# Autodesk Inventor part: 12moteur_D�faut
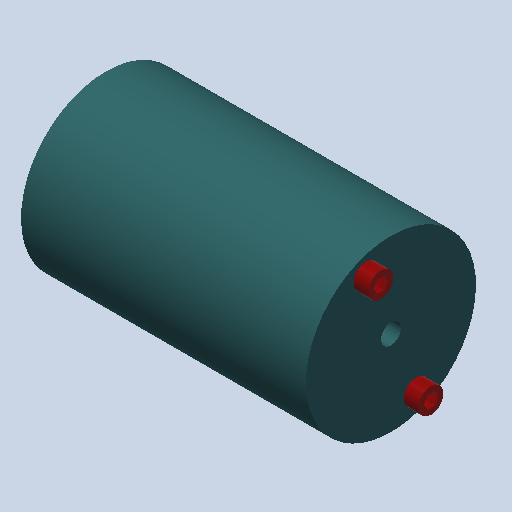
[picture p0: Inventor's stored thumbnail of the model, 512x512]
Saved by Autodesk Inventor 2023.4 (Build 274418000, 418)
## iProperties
Created: 2011-01
Part Number: 12moteur_D�faut
Document SubType Name: Modeling
Designer: eric
Density: 1 g/cm^3
Mass: 414.235 g
Surface Area: 324.185 cm^2
Volume: 414.235 cm^3
Material: Générique
Appearance: 64,128,128
Author: eric
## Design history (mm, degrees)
feature "Base1"
node "Corps solides"
node "Corps surfaciques"
node "Solide1"
